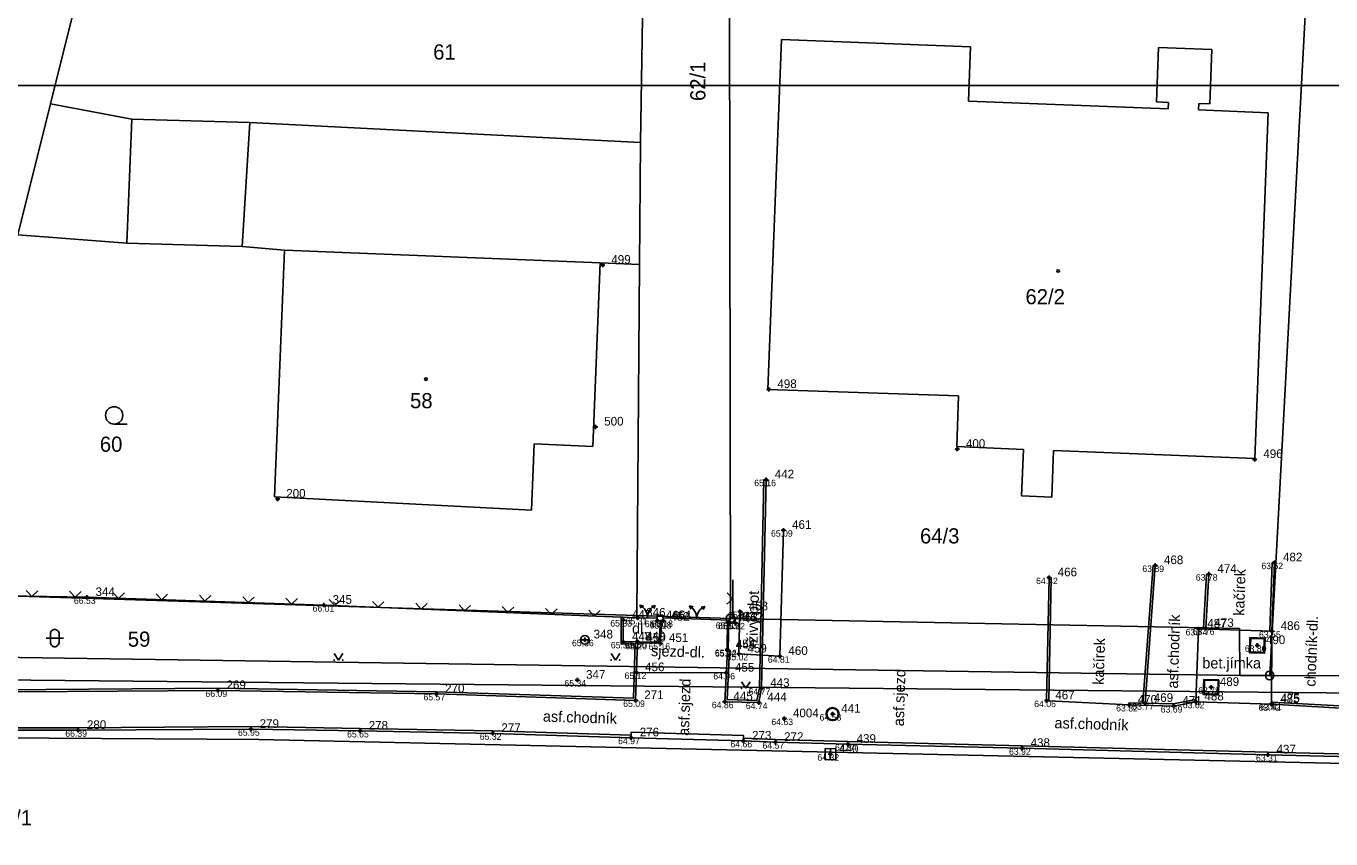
# Model space of a CAD drawing. Extents: x -454285 to -453563, y -1108687 to -1108249.
# Drawn here: x -453869.2 to -453808.9, y -1108476.5 to -1108439 of the extents above; entities that cross this region are included whole.
import ezdxf

# ---------------------------------------------------------------- set-up
doc = ezdxf.new("R2010")
doc.units = 0
for name, color, linetype in [('1', 7, 'Continuous'), ('14', 7, 'Continuous'), ('15', 7, 'Continuous'), ('16', 7, 'Continuous'), ('2', 7, 'Continuous'), ('23', 7, 'Continuous'), ('25', 7, 'Continuous'), ('28', 7, 'Continuous'), ('beton', 7, 'Continuous'), ('BODY_T1_2018', 7, 'Continuous'), ('CISLA_T1_2018', 7, 'Continuous'), ('obrubník', 7, 'Continuous'), ('oplocení', 7, 'Continuous'), ('rozhraní', 7, 'Continuous'), ('rámy', 7, 'Continuous'), ('sloup', 7, 'Continuous'), ('T', 7, 'Continuous'), ('uliční vpusť', 7, 'Continuous'), ('VYSKY_T1_2018', 7, 'Continuous'), ('zeleň', 7, 'Continuous'), ('šachtice', 7, 'Continuous'), ('živý plot', 7, 'Continuous')]:
    doc.layers.add(name, color=color, linetype=linetype)

# ---------------------------------------------------------------- blocks, each defined once
blk = doc.blocks.new('Z402')
for start, end in [(0, 180), (180, 0)]:
    blk.add_arc((0, 0), 0.15, start, end)
blk = doc.blocks.new('Z105')
for radius in [0.5, 0.01]:
    blk.add_circle((0, 0), radius)
blk = doc.blocks.new('Z3160')
for p, q in [((-0.5, 1.6), (-0.4, 1.8)), ((-0.5, 0.4), (-0.5, 1.6)), ((-0.4, 1.8), (-0.3, 1.9)), ((-0.3, 1.9), (-0.1, 2)), ((-0.1, 2), (0.1, 2)), ((0.1, 2), (0.3, 1.9)), ((0.3, 1.9), (0.4, 1.8)), ((0.4, 1.8), (0.5, 1.6)), ((0.5, 1.6), (0.5, 0.4)), ((-1, 1), (1, 1)), ((-0.4, 0.2), (-0.5, 0.4)), ((-0.3, 0.1), (-0.4, 0.2)), ((-0.1, 0), (-0.3, 0.1)), ((0.1, 0), (-0.1, 0)), ((0.3, 0.1), (0.1, 0)), ((0.4, 0.2), (0.3, 0.1)), ((0.5, 0.4), (0.4, 0.2))]:
    blk.add_line(p, q)
blk = doc.blocks.new('Z3040')
blk.add_line((1.5, 0), (0, 0))
blk.add_circle((0, 1), 1)
blk = doc.blocks.new('EL.SLOUP')
blk.add_line((0.4, 0), (-0.4, 0))
blk.add_line((0.4, 0), (-0.4, 0))
blk.add_lwpolyline([(0.4, 0), (-0.4, 0)])
blk.add_lwpolyline([(0.4, 0), (-0.4, 0)])
blk.add_circle((0, 0), 0.4)
blk.add_circle((0, 0), 0.4)
for start, end in [(270, 0), (270, 0), (180, 270), (180, 270)]:
    blk.add_arc((0, 0), 0.4, start, end)
blk = doc.blocks.new('šachtice_kruh_velká')
for radius in [0.5, 0.495, 0.495, 0.455, 0.455, 0.45]:
    blk.add_circle((0, 0), radius)
blk = doc.blocks.new('vpusť')
for p, q in [((0.25, 0.25), (-0.25, 0.25)), ((-0.25, 0.25), (-0.25, -0.25)), ((-0.25, 0), (0.25, 0)), ((0.25, -0.25), (0.25, 0.25)), ((-0.25, -0.25), (0.25, -0.25))]:
    blk.add_line(p, q)
blk = doc.blocks.new('šachtice_hranatá_velká')
for p, q in [((-0.5, 0.5), (0.5, 0.5)), ((-0.5, -0.5), (-0.5, 0.5)), ((0.45, 0.45), (-0.45, 0.45)), ((-0.45, 0.45), (-0.45, -0.45)), ((0.45, -0.45), (0.45, 0.45)), ((0.5, 0.5), (0.5, -0.5)), ((0.5, -0.5), (-0.5, -0.5)), ((-0.45, -0.45), (0.45, -0.45))]:
    blk.add_line(p, q)
for points in [[(-0.5, 0.5), (0.5, 0.5), (0.5, -0.5), (-0.5, -0.5)], [(-0.45, 0.45), (0.45, 0.45), (0.45, -0.45), (-0.45, -0.45)]]:
    blk.add_lwpolyline(points, close=True)
blk = doc.blocks.new('PLOT05')
for q in [(-0.265, 0.265), (0.265, 0.265)]:
    blk.add_line((0, 0), q)
blk = doc.blocks.new('BRANKA')
for p, q in [((-0.351, 0.589), (-0.179, 0.552)), ((-0.351, 0.589), (-0.284, 0.449)), ((0.361, 0.583), (0.188, 0.549)), ((0.361, 0.583), (0.291, 0.445))]:
    blk.add_line(p, q)
for centre, start, end in [((-0.618, 0.03), 357.17506, 64.46884), ((0.619, 0.02), 114.58945, 181.88322)]:
    blk.add_arc(centre, 0.619, start, end)
blk = doc.blocks.new('PARK')
for p, q in [((0, 0), (-1, 1.5)), ((1, 1.5), (0, 0))]:
    blk.add_line(p, q)
for centre, start, end in [((-1, 0), 0, 180), ((1, 0), 0, 180), ((1, 0), 180, 0), ((-1, 0), 180, 0)]:
    blk.add_arc(centre, 0.05, start, end)
blk = doc.blocks.new('POINT_DISPLAY')
for p, q in [((-0.1, 0), (0.1, 0)), ((0, -0.1), (0, 0.1))]:
    blk.add_line(p, q)
blk.add_circle((0, 0), 0.05)
blk = doc.blocks.new('t1_2018')
at = {"layer": 'BODY_T1_2018'}
for p in [(-453842.57, -1108449.99), (-453834.9, -1108455.73), (-453842.9, -1108457.46), (-453826.19, -1108458.49), (-453812.45, -1108458.96), (-453835.02, -1108459.9), (-453857.59, -1108460.79), (-453834.22, -1108462.23), (-453817.04, -1108463.86), (-453814.57, -1108464.26), (-453811.54, -1108463.73), (-453821.95, -1108464.42), (-453866.4, -1108465.33), (-453855.45, -1108465.69), (-453836.23, -1108465.99), (-453841.62, -1108466.38), (-453840.96, -1108466.28), (-453840.05, -1108466.41), (-453839.85, -1108466.47), (-453839.78, -1108466.4), (-453836.8, -1108466.48), (-453836.69, -1108466.5), (-453836.45, -1108466.51), (-453843.39, -1108467.29), (-453815.04, -1108466.79), (-453814.71, -1108466.76), (-453811.65, -1108466.9), (-453841.62, -1108467.39), (-453840.97, -1108467.37), (-453840.95, -1108467.43), (-453839.91, -1108467.45), (-453836.82, -1108467.74), (-453836.81, -1108467.77), (-453836.28, -1108467.94), (-453812.33, -1108467.55), (-453834.39, -1108468.05), (-453843.74, -1108469.15), (-453841.01, -1108468.8), (-453836.86, -1108468.82), (-453860.35, -1108469.63), (-453835.23, -1108469.53), (-453814.46, -1108469.48), (-453850.25, -1108469.79), (-453841.05, -1108470.09), (-453836.93, -1108470.15), (-453835.36, -1108470.19), (-453822.06, -1108470.1), (-453818.25, -1108470.3), (-453817.51, -1108470.22), (-453816.19, -1108470.35), (-453815.17, -1108470.15), (-453811.67, -1108470.27), (-453811.65, -1108470.23), (-453834.18, -1108470.93), (-453831.95, -1108470.72), (-453866.8, -1108471.47), (-453858.82, -1108471.42), (-453853.78, -1108471.5), (-453847.65, -1108471.61), (-453841.26, -1108471.81), (-453836.07, -1108471.96), (-453834.59, -1108472.02), (-453831.24, -1108472.11), (-453832.05, -1108472.57), (-453823.2, -1108472.3), (-453811.84, -1108472.6)]:
    blk.add_blockref('POINT_DISPLAY', p, dxfattribs=at)
at = {"layer": 'CISLA_T1_2018'}
for s, p in [('499', (-453842.17, -1108449.93)), ('498', (-453834.5, -1108455.67)), ('500', (-453842.5, -1108457.4)), ('400', (-453825.79, -1108458.43)), ('496', (-453812.05, -1108458.9)), ('442', (-453834.62, -1108459.84)), ('200', (-453857.19, -1108460.73)), ('461', (-453833.82, -1108462.17)), ('468', (-453816.64, -1108463.8)), ('482', (-453811.14, -1108463.67)), ('466', (-453821.55, -1108464.36)), ('474', (-453814.17, -1108464.2)), ('344', (-453866, -1108465.27)), ('345', (-453855.05, -1108465.63)), ('447', (-453841.22, -1108466.32)), ('346', (-453840.56, -1108466.22)), ('465', (-453839.65, -1108466.35)), ('452', (-453839.45, -1108466.41)), ('464', (-453839.38, -1108466.34)), ('453', (-453836.4, -1108466.42)), ('463', (-453836.29, -1108466.44)), ('458', (-453835.83, -1108465.93)), ('462', (-453836.05, -1108466.45)), ('487', (-453814.64, -1108466.73)), ('473', (-453814.31, -1108466.7)), ('486', (-453811.25, -1108466.84)), ('348', (-453842.99, -1108467.23)), ('448', (-453841.22, -1108467.33)), ('449', (-453840.57, -1108467.31)), ('450', (-453840.55, -1108467.37)), ('451', (-453839.51, -1108467.39)), ('490', (-453811.93, -1108467.49)), ('454', (-453836.42, -1108467.68)), ('446', (-453836.41, -1108467.71)), ('459', (-453835.88, -1108467.88)), ('460', (-453833.99, -1108467.99)), ('456', (-453840.61, -1108468.74)), ('455', (-453836.46, -1108468.76)), ('347', (-453843.34, -1108469.09)), ('489', (-453814.06, -1108469.42)), ('269', (-453859.95, -1108469.57)), ('270', (-453849.85, -1108469.73)), ('271', (-453840.65, -1108470.03)), ('443', (-453834.83, -1108469.47)), ('467', (-453821.66, -1108470.04)), ('445', (-453836.53, -1108470.09)), ('444', (-453834.96, -1108470.13)), ('470', (-453817.85, -1108470.24)), ('469', (-453817.11, -1108470.16)), ('471', (-453815.79, -1108470.29)), ('488', (-453814.77, -1108470.09)), ('485', (-453811.27, -1108470.21)), ('475', (-453811.25, -1108470.17)), ('4004', (-453833.78, -1108470.87)), ('441', (-453831.55, -1108470.66)), ('280', (-453866.4, -1108471.41)), ('279', (-453858.42, -1108471.36)), ('278', (-453853.38, -1108471.44)), ('277', (-453847.25, -1108471.55)), ('276', (-453840.86, -1108471.75)), ('273', (-453835.67, -1108471.9)), ('272', (-453834.19, -1108471.96)), ('439', (-453830.84, -1108472.05)), ('438', (-453822.8, -1108472.24)), ('440', (-453831.65, -1108472.51)), ('437', (-453811.44, -1108472.54))]:
    blk.add_text(s, height=0.4, dxfattribs=at).set_placement(p)
at = {"layer": 'VYSKY_T1_2018'}
for s, p in [('65.16', (-453835.57, -1108460.2)), ('65.09', (-453834.795, -1108462.53)), ('63.89', (-453817.64, -1108464.16)), ('63.62', (-453812.14, -1108464.03)), ('64.42', (-453822.55, -1108464.72)), ('63.78', (-453815.17, -1108464.56)), ('66.53', (-453867, -1108465.63)), ('66.01', (-453855.975, -1108465.99)), ('65.13', (-453836.78, -1108466.29)), ('65.33', (-453842.22, -1108466.68)), ('65.31', (-453841.51, -1108466.58)), ('65.30', (-453840.625, -1108466.71)), ('65.18', (-453840.4, -1108466.77)), ('65.18', (-453840.33, -1108466.7)), ('65.13', (-453837.35, -1108466.78)), ('65.13', (-453837.24, -1108466.8)), ('65.12', (-453837, -1108466.81)), ('63.74', (-453815.64, -1108467.09)), ('63.76', (-453815.31, -1108467.06)), ('63.55', (-453812.25, -1108467.2)), ('65.36', (-453843.99, -1108467.59)), ('65.30', (-453842.195, -1108467.69)), ('65.30', (-453841.545, -1108467.67)), ('65.20', (-453841.525, -1108467.73)), ('65.16', (-453840.46, -1108467.75)), ('65.04', (-453837.395, -1108468.04)), ('65.02', (-453837.385, -1108468.07)), ('63.80', (-453812.905, -1108467.85)), ('65.02', (-453836.855, -1108468.24)), ('64.81', (-453834.94, -1108468.35)), ('65.12', (-453841.56, -1108469.1)), ('64.96', (-453837.46, -1108469.12)), ('66.09', (-453860.925, -1108469.93)), ('65.34', (-453844.34, -1108469.45)), ('64.77', (-453835.83, -1108469.83)), ('63.78', (-453815.06, -1108469.78)), ('65.57', (-453850.85, -1108470.09)), ('65.09', (-453841.625, -1108470.39)), ('64.86', (-453837.53, -1108470.45)), ('64.74', (-453835.96, -1108470.49)), ('64.06', (-453822.635, -1108470.4)), ('63.77', (-453818.11, -1108470.52)), ('63.62', (-453815.77, -1108470.45)), ('63.41', (-453812.2, -1108470.53)), ('64.53', (-453832.55, -1108471.02)), ('63.82', (-453818.85, -1108470.6)), ('63.69', (-453816.79, -1108470.65)), ('63.42', (-453812.27, -1108470.57)), ('65.95', (-453859.42, -1108471.72)), ('64.63', (-453834.78, -1108471.23)), ('66.39', (-453867.4, -1108471.77)), ('65.65', (-453854.38, -1108471.8)), ('65.32', (-453848.25, -1108471.91)), ('64.97', (-453841.86, -1108472.11)), ('64.66', (-453836.67, -1108472.26)), ('64.57', (-453835.19, -1108472.32)), ('64.32', (-453832.65, -1108472.87)), ('64.34', (-453831.84, -1108472.41)), ('63.92', (-453823.8, -1108472.6)), ('63.31', (-453812.39, -1108472.9))]:
    blk.add_text(s, height=0.3, dxfattribs=at).set_placement(p)

msp = doc.modelspace()

# ---------------------------------------------------------------- linework, layer by layer
at = {"layer": '1'}
for p, q in [((-453811.757, -1108468.941), (-453809.507, -1108427.091)), ((-453836.737, -1108428.431), (-453836.667, -1108466.301)), ((-453840.827, -1108444.331), (-453840.597, -1108430.051)), ((-453868.087, -1108442.551), (-453865.887, -1108433.791)), ((-453834.937, -1108455.731), (-453834.317, -1108439.581)), ((-453834.317, -1108439.581), (-453825.577, -1108439.921)), ((-453825.577, -1108439.921), (-453825.677, -1108442.431)), ((-453816.987, -1108442.461), (-453816.897, -1108439.951)), ((-453816.897, -1108439.951), (-453814.427, -1108440.041)), ((-453814.427, -1108440.041), (-453814.517, -1108442.551)), ((-453825.677, -1108442.431), (-453816.447, -1108442.781)), ((-453816.437, -1108442.481), (-453816.987, -1108442.461)), ((-453816.447, -1108442.781), (-453816.437, -1108442.481)), ((-453869.597, -1108448.591), (-453868.087, -1108442.551)), ((-453864.327, -1108443.261), (-453868.087, -1108442.551)), ((-453815.037, -1108442.531), (-453815.047, -1108442.831)), ((-453815.047, -1108442.831), (-453811.827, -1108442.961)), ((-453814.517, -1108442.551), (-453815.037, -1108442.531)), ((-453811.827, -1108442.961), (-453812.447, -1108458.921)), ((-453858.877, -1108443.411), (-453864.327, -1108443.261)), ((-453840.827, -1108444.331), (-453858.877, -1108443.411)), ((-453840.867, -1108449.971), (-453840.827, -1108444.331)), ((-453869.597, -1108448.591), (-453864.557, -1108448.981)), ((-453864.557, -1108448.981), (-453859.227, -1108449.131)), ((-453857.267, -1108449.301), (-453859.227, -1108449.131)), ((-453857.267, -1108449.301), (-453857.727, -1108460.691)), ((-453843.027, -1108458.361), (-453842.687, -1108449.891)), ((-453842.687, -1108449.891), (-453840.867, -1108449.971)), ((-453840.987, -1108466.171), (-453840.867, -1108449.971)), ((-453826.127, -1108456.031), (-453834.937, -1108455.731)), ((-453826.217, -1108458.371), (-453826.127, -1108456.031)), ((-453845.867, -1108461.311), (-453845.737, -1108458.251)), ((-453845.737, -1108458.251), (-453843.027, -1108458.361)), ((-453823.137, -1108458.501), (-453826.217, -1108458.371)), ((-453823.227, -1108460.651), (-453823.137, -1108458.501)), ((-453821.737, -1108458.551), (-453821.827, -1108460.701)), ((-453812.447, -1108458.921), (-453821.737, -1108458.551)), ((-453845.867, -1108461.311), (-453857.727, -1108460.691)), ((-453821.827, -1108460.701), (-453823.227, -1108460.651)), ((-453873.747, -1108465.151), (-453840.987, -1108466.171)), ((-453836.667, -1108466.301), (-453840.987, -1108466.171)), ((-453836.667, -1108466.301), (-453813.157, -1108466.771)), ((-453813.157, -1108466.771), (-453813.137, -1108468.941)), ((-453813.137, -1108468.941), (-453874.467, -1108468.031)), ((-453897.257, -1108468.871), (-453776.927, -1108470.061)), ((-453813.137, -1108468.941), (-453811.757, -1108468.941)), ((-453803.127, -1108468.961), (-453811.757, -1108468.941))]:
    msp.add_line(p, q, dxfattribs=at)
at = {"layer": '2'}
for p, q in [((-453864.327, -1108443.261), (-453864.557, -1108448.981)), ((-453858.877, -1108443.411), (-453859.227, -1108449.131)), ((-453842.687, -1108449.891), (-453857.267, -1108449.301)), ((-453874.387, -1108471.791), (-453858.457, -1108471.891)), ((-453670.227, -1108476.061), (-453858.457, -1108471.891))]:
    msp.add_line(p, q, dxfattribs=at)
at = {"layer": 'beton'}
msp.add_lwpolyline([(-453815.04, -1108466.79), (-453815.17, -1108470.15), (-453811.67, -1108470.27), (-453811.65, -1108466.9)], close=True, dxfattribs=at)
at = {"layer": 'obrubník'}
for points in [[(-453835.02, -1108459.9), (-453835.23, -1108469.53), (-453835.36, -1108470.19), (-453836.93, -1108470.15), (-453836.81, -1108467.77), (-453836.71, -1108467.775), (-453836.825, -1108470.053), (-453835.442, -1108470.088), (-453835.33, -1108469.519), (-453835.12, -1108459.898)], [(-453817.14, -1108463.853), (-453817.61, -1108470.216), (-453818.248, -1108470.2), (-453818.25, -1108470.3), (-453816.19, -1108470.35), (-453815.17, -1108470.15), (-453815.189, -1108470.052), (-453816.199, -1108470.25), (-453817.51, -1108470.218), (-453817.04, -1108463.86)], [(-453811.54, -1108463.73), (-453811.65, -1108466.9), (-453811.75, -1108466.897), (-453811.64, -1108463.727)], [(-453821.95, -1108464.42), (-453822.06, -1108470.1), (-453821.96, -1108470.105), (-453821.85, -1108464.422)], [(-453814.67, -1108464.254), (-453814.81, -1108466.75), (-453814.71, -1108466.76), (-453814.57, -1108464.26)], [(-453836.748, -1108466.378), (-453836.77, -1108467.741), (-453836.82, -1108467.74), (-453836.798, -1108466.376)], [(-453797.117, -1108472.86), (-453804.097, -1108472.66), (-453811.837, -1108472.48), (-453823.197, -1108472.18), (-453831.237, -1108471.99), (-453834.586, -1108471.9), (-453836.066, -1108471.84), (-453836.07, -1108471.96), (-453834.59, -1108472.02), (-453831.24, -1108472.11), (-453823.2, -1108472.3), (-453811.84, -1108472.6), (-453804.1, -1108472.78), (-453797.12, -1108472.98)]]:
    msp.add_lwpolyline(points, dxfattribs=at)
for points in [[(-453841.72, -1108466.249), (-453841.72, -1108467.493), (-453841.073, -1108467.473), (-453841.147, -1108469.987), (-453850.248, -1108469.69), (-453860.35, -1108469.53), (-453874.271, -1108469.63), (-453874.27, -1108469.73), (-453860.35, -1108469.63), (-453850.25, -1108469.79), (-453841.05, -1108470.09), (-453840.97, -1108467.37), (-453841.62, -1108467.39), (-453841.62, -1108466.253)], [(-453839.896, -1108466.404), (-453839.957, -1108467.399), (-453840.949, -1108467.38), (-453840.95, -1108467.43), (-453839.91, -1108467.45), (-453839.846, -1108466.402)], [(-453807.665, -1108470.39), (-453811.665, -1108470.17), (-453811.67, -1108470.27), (-453807.67, -1108470.49)], [(-453841.256, -1108471.69), (-453847.647, -1108471.49), (-453853.778, -1108471.38), (-453858.819, -1108471.3), (-453866.8, -1108471.35), (-453875.091, -1108471.35), (-453875.09, -1108471.47), (-453866.8, -1108471.47), (-453858.82, -1108471.42), (-453853.78, -1108471.5), (-453847.65, -1108471.61), (-453841.26, -1108471.81)], [(-453841.26, -1108471.81), (-453836.07, -1108471.96), (-453836.063, -1108471.71), (-453841.253, -1108471.56)]]:
    msp.add_lwpolyline(points, close=True, dxfattribs=at)
at = {"layer": 'oplocení'}
for points in [[(-453836.56, -1108466.265), (-453836.563, -1108464.526)], [(-453873.81, -1108465.2), (-453866.4, -1108465.33), (-453855.45, -1108465.69), (-453840.96, -1108466.28)], [(-453840.96, -1108466.28), (-453840.055, -1108466.285)], [(-453839.785, -1108466.275), (-453836.685, -1108466.38)]]:
    msp.add_lwpolyline(points, dxfattribs=at)
for points in [[(-453839.789, -1108466.15), (-453840.059, -1108466.16), (-453840.05, -1108466.41), (-453839.78, -1108466.4)], [(-453836.44, -1108466.27), (-453836.68, -1108466.26), (-453836.69, -1108466.5), (-453836.45, -1108466.51)]]:
    msp.add_lwpolyline(points, close=True, dxfattribs=at)
at = {"layer": 'rozhraní'}
for points in [[(-453841.01, -1108468.8), (-453836.86, -1108468.82)], [(-453821.96, -1108470.105), (-453818.25, -1108470.3)]]:
    msp.add_lwpolyline(points, dxfattribs=at)
at = {"layer": 'rámy'}
msp.add_lwpolyline([(-453889.309, -1108441.707), (-453790.141, -1108441.707), (-453790.141, -1108501.759), (-453889.309, -1108501.759)], close=True, dxfattribs=at)
at = {"layer": 'živý plot'}
msp.add_lwpolyline([(-453836.23, -1108465.99), (-453836.28, -1108467.94), (-453834.39, -1108468.05), (-453834.22, -1108462.23)], dxfattribs=at)

# ---------------------------------------------------------------- block references
msp.add_blockref('t1_2018', (0, 0))
at = {"layer": '23', "xscale": 0.4, "yscale": 0.4000000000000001}
for name, p in [('Z3040', (-453865.14, -1108457.329)), ('Z3160', (-453867.887, -1108467.611))]:
    msp.add_blockref(name, p, dxfattribs=at)
at = {"layer": '25', "xscale": 0.4, "yscale": 0.4000000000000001}
for p in [(-453821.528, -1108450.264), (-453850.737, -1108455.259)]:
    msp.add_blockref('Z402', p, dxfattribs=at)
at = {"layer": '28', "xscale": 0.4, "yscale": 0.4000000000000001}
for p in [(-453836.667, -1108466.301), (-453811.757, -1108468.941)]:
    msp.add_blockref('Z105', p, dxfattribs=at)
at = {"layer": 'oplocení'}
for name, p, rotation in [('PLOT05', (-453868.942, -1108465.285), -1.0050860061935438), ('PLOT05', (-453866.942, -1108465.32), -1.0050860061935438), ('PLOT05', (-453864.943, -1108465.378), -1.88301861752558), ('PLOT05', (-453862.944, -1108465.444), -1.88301861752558), ('PLOT05', (-453860.945, -1108465.509), -1.88301861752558), ('PLOT05', (-453858.946, -1108465.575), -1.88301861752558), ('PLOT05', (-453856.947, -1108465.641), -1.88301861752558), ('PLOT05', (-453854.948, -1108465.71), -2.3316664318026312), ('PLOT05', (-453836.562, -1108465.396), 87.66837000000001), ('PLOT05', (-453852.95, -1108465.792), -2.3316664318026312), ('PLOT05', (-453850.952, -1108465.873), -2.3316664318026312), ('PLOT05', (-453848.953, -1108465.955), -2.3316664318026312), ('PLOT05', (-453846.955, -1108466.036), -2.3316664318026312), ('PLOT05', (-453844.957, -1108466.117), -2.3316664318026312), ('PLOT05', (-453842.958, -1108466.199), -2.3316664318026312), ('BRANKA', (-453840.507, -1108466.283), -0.32183729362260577), ('BRANKA', (-453838.235, -1108466.328), -1.9385741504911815)]:
    msp.add_blockref(name, p, dxfattribs=dict(at, rotation=rotation))
at = {"layer": 'sloup', "xscale": 0.5, "yscale": 0.5}
msp.add_blockref('EL.SLOUP', (-453843.39, -1108467.29), dxfattribs=at)
at = {"layer": 'uliční vpusť', "rotation": 88.46108057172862}
msp.add_blockref('vpusť', (-453832.05, -1108472.57), dxfattribs=at)
at = {"layer": 'zeleň', "xscale": 0.2, "yscale": 0.20000000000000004}
for p in [(-453854.78, -1108468.231), (-453841.981, -1108468.231), (-453835.954, -1108469.527)]:
    msp.add_blockref('PARK', p, dxfattribs=at)
at = {"layer": 'šachtice', "xscale": 0.7, "yscale": 0.7000000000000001, "rotation": -91.96365753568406}
for p in [(-453812.33, -1108467.55), (-453814.46, -1108469.48)]:
    msp.add_blockref('šachtice_hranatá_velká', p, dxfattribs=at)
at = {"layer": 'šachtice', "xscale": 0.6, "yscale": 0.6}
msp.add_blockref('šachtice_kruh_velká', (-453831.95, -1108470.72), dxfattribs=at)

# ---------------------------------------------------------------- texts
at = {"layer": '14'}
for s, p in [('61', (-453850.403, -1108440.501)), ('60', (-453865.802, -1108458.611)), ('64/3', (-453827.911, -1108462.844)), ('59', (-453864.51, -1108467.611))]:
    msp.add_text(s, height=0.7, dxfattribs=at).set_placement(p)
msp.add_text('62/1', height=0.7, rotation=90.009, dxfattribs=at).set_placement((-453837.826, -1108442.417))
at = {"layer": '15'}
for s, p in [('62/2', (-453823.04, -1108451.801)), ('58', (-453851.47, -1108456.601))]:
    msp.add_text(s, height=0.7, dxfattribs=at).set_placement(p)
at = {"layer": '16'}
msp.add_text('2410/1', height=0.7, rotation=0.1968, dxfattribs=at).set_placement((-453871.797, -1108475.861))
at = {"layer": 'T'}
for s, rotation, p in [('kačírek', 88.31532, (-453812.934, -1108466.186)), ('živý plot', 88.31532, (-453835.416, -1108467.45)), ('asf.chodník', 88.31532, (-453815.994, -1108469.548)), ('chodník-dl.', 87.86726, (-453809.641, -1108469.46)), ('kačírek', 88.31532, (-453819.424, -1108469.375)), ('sjezd-dl.', 358.20729, (-453840.342, -1108468.042)), ('asf.sjezd', 88.31532, (-453828.656, -1108471.287)), ('asf.sjezd', 88.31532, (-453838.582, -1108471.729)), ('asf.chodník', 358.20729, (-453845.339, -1108471.066)), ('asf.chodník', 358.20729, (-453821.704, -1108471.372))]:
    msp.add_text(s, height=0.5, rotation=rotation, dxfattribs=at).set_placement(p)
for s, p in [('dl.', (-453841.213, -1108467.015)), ('bet.jímka', (-453814.869, -1108468.614))]:
    msp.add_text(s, height=0.5, dxfattribs=at).set_placement(p)

doc.saveas('drawing.dxf')
